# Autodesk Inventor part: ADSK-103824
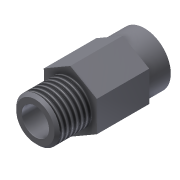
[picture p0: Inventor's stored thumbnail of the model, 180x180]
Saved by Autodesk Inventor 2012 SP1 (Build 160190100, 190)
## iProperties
Shininess: 27.0
Created: 2001-04
Part Number: ADSK-103824
Document SubType Name: Modeling
Designer: Administrator
Stock Number: ADSK-103824
Density: 1 g/cm^3
Material: Default
Density: 0.0
Volumn: 0.0
Area: 0.0
PropertySet Name: Model Information
Control State: 0
Master: False
Checked Out: False
Author: Administrator
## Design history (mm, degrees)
sketch "Sketch1"
  geometry: C1 r 6.35 at (0, 0)
  constraints: 1 centre point
  dimensions: "d0" = 12.7 diameter of C1
extrude "Extrusion1" new body sketch "Sketch1" distance "d1" = 10.16; taper "d2" = 0 deg
sketch "Sketch2"
  geometry: L1 (3.608, 9.95)-(10.154, 3.935); L2 (10.154, 3.935)-(8.218, -4.741); L3 (8.218, -4.741)-(-0.264, -7.403); L4 (-0.264, -7.403)-(-6.81, -1.388); L5 (-6.81, -1.388)-(-4.874, 7.288); L6 (-4.874, 7.288)-(3.608, 9.95); C1 r 6.35 at (1.672, 1.274) reference; A1 r 8.89 centre (1.672, 1.274) between (3.608, 9.95) and (10.154, 3.935)
  constraints: 12 end point, 6 point on circle, 3 equal length, 3 parallel, 1 centre point, 1 concentric
  dimensions: "d3" = 17.78 diameter of A1 (derived)
feature "Hexagon_corners_join1" sketch "Sketch2"
sketch "Sketch3"
  geometry: C1 r 6.35 at (4.445, -7.699) reference; C2 r 7.62 at (4.445, -7.699)
  constraints: 1 centre point, 1 coincident
  dimensions: "d5" = 15.24 diameter of C2
extrude "Extrusion2" join sketch "Sketch3" distance "d6" = 6.35; taper "d7" = 0 deg
sketch "Sketch4"
  geometry: C1 r 6.35 at (0, 0) reference; 1 further point
  constraints: 1 coincident
hole "Hole1" sketch "Sketch4" at (0, 0) diameter "d8" = 7.9375; stored, may be unused: countersink angle "d12" = 60 deg, drill point angle "d14" = 118 deg; dims "d9" = 12.7, "d10" = 9.525, "d11" = 6.35, "d13" = 19.05
chamfer "Chamfer1" distance "d15" = 0.79375; stored, may be unused: second distance "d16" = 0.79375, angle "d19" = 45 deg
thread "Thread1" dims "d17" = 25.4, "d18" = 0
body "Solid1"
